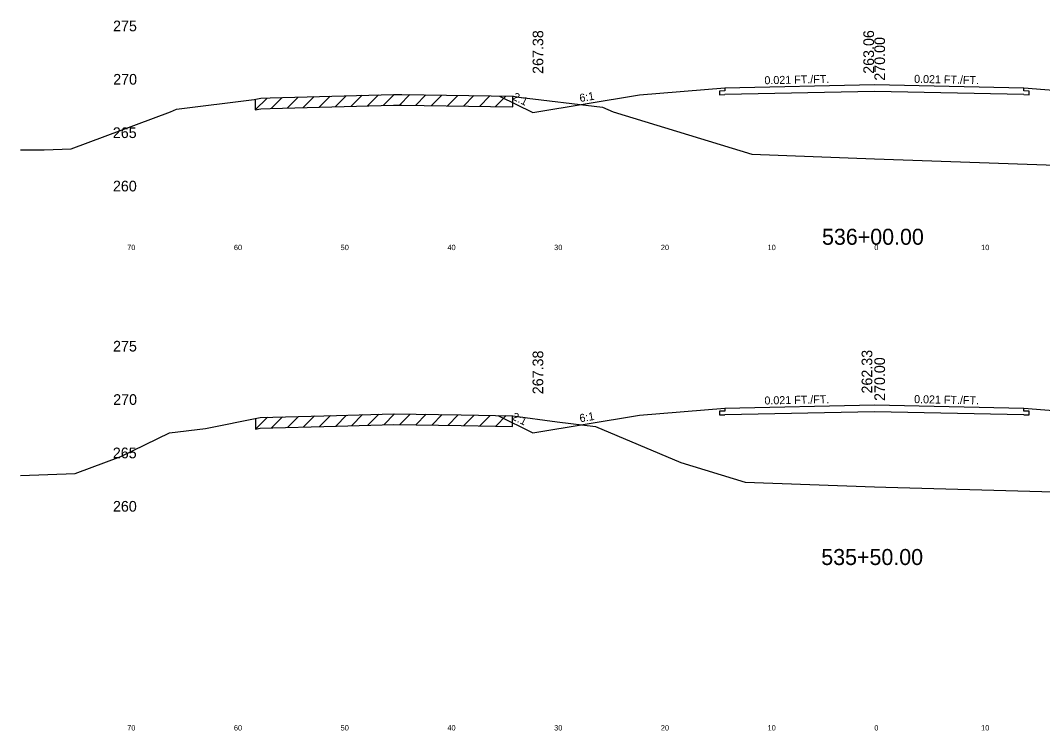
# Model space of a CAD drawing. Extents: x 1000 to 1162, y 999 to 8520.
# Drawn here: x 1000 to 1095.8, y 5599.5 to 5666 of the extents above; entities that cross this region are included whole.
import ezdxf

# ---------------------------------------------------------------- set-up
doc = ezdxf.new("R2010")
doc.units = 0
for name, color, linetype in [('Level 10', 7, 'Continuous'), ('Level 11', 7, 'Continuous'), ('Level 12', 7, 'Continuous'), ('Level 3', 7, 'Continuous'), ('Level 32', 7, 'Continuous'), ('Level 33', 7, 'Continuous'), ('Level 56', 7, 'Continuous'), ('Level 59', 7, 'Continuous'), ('Level 6', 7, 'Continuous'), ('Level 60', 7, 'Continuous'), ('Level 61', 7, 'Continuous'), ('Level 7', 7, 'Continuous')]:
    doc.layers.add(name, color=color, linetype=linetype)

msp = doc.modelspace()

# ---------------------------------------------------------------- linework, layer by layer
at = {"layer": 'Level 11'}
for p, q in [((1066, 5659.409), (1065.5, 5659.398)), ((1065.5, 5659.398), (1065.5, 5659.058)), ((1066, 5659.709), (1066, 5659.409)), ((1094, 5659.409), (1094, 5659.709)), ((1094.5, 5659.398), (1094, 5659.409)), ((1094.5, 5659.058), (1094.5, 5659.398)), ((1065.5, 5659.058), (1066, 5659.069)), ((1094, 5659.069), (1094.5, 5659.058)), ((1066, 5629.709), (1066, 5629.409)), ((1094, 5629.409), (1094, 5629.709)), ((1066, 5629.409), (1065.5, 5629.398)), ((1065.5, 5629.398), (1065.5, 5629.058)), ((1065.5, 5629.058), (1066, 5629.069)), ((1094.5, 5629.398), (1094, 5629.409)), ((1094, 5629.069), (1094.5, 5629.058)), ((1094.5, 5629.058), (1094.5, 5629.398))]:
    msp.add_line(p, q, dxfattribs=at)
at = {"layer": 'Level 12'}
for p, q in [((1080, 5659.36), (1066, 5659.069)), ((1094, 5659.069), (1080, 5659.36)), ((1080, 5629.36), (1066, 5629.069)), ((1094, 5629.069), (1080, 5629.36))]:
    msp.add_line(p, q, dxfattribs=at)
at = {"layer": 'Level 59'}
for p, q in [((1066, 5659.709), (1080, 5660)), ((1080, 5660), (1094, 5659.709)), ((1066, 5629.709), (1080, 5630)), ((1080, 5630), (1094, 5629.709))]:
    msp.add_line(p, q, dxfattribs=at)
at = {"layer": 'Level 6'}
for p, q in [((1058, 5659.042), (1066, 5659.709)), ((1094, 5659.709), (1102, 5659.042)), ((1058, 5629.042), (1066, 5629.709)), ((1094, 5629.709), (1102, 5629.042))]:
    msp.add_line(p, q, dxfattribs=at)
at = {"layer": 'Level 60'}
for p, q in [((1014.617, 5657.714), (1021.896, 5658.608)), ((1021.896, 5658.608), (1022.517, 5658.732)), ((1022.517, 5658.732), (1023.383, 5658.756)), ((1023.383, 5658.756), (1034.954, 5659.091)), ((1034.954, 5659.091), (1035.735, 5659.078)), ((1035.735, 5659.078), (1046.182, 5658.911)), ((1046.182, 5658.911), (1046.699, 5658.84)), ((1046.699, 5658.84), (1054.528, 5657.893)), ((1014.061, 5657.443), (1014.617, 5657.714)), ((1054.528, 5657.893), (1055.542, 5657.466)), ((1055.542, 5657.466), (1068.523, 5653.474)), ((1004.757, 5654), (1014.061, 5657.443)), ((1000, 5653.891), (1002.221, 5653.908)), ((1002.221, 5653.908), (1004.757, 5654)), ((1068.523, 5653.474), (1080, 5653.063)), ((1080, 5653.063), (1097.018, 5652.454)), ((1017.337, 5627.797), (1022.466, 5628.822)), ((1022.466, 5628.822), (1029.616, 5629.016)), ((1029.616, 5629.016), (1034.963, 5629.171)), ((1034.963, 5629.171), (1041.299, 5629.063)), ((1041.299, 5629.063), (1046.116, 5628.986)), ((1046.116, 5628.986), (1050.276, 5628.42)), ((1013.973, 5627.384), (1017.337, 5627.797)), ((1050.276, 5628.42), (1053.891, 5627.983)), ((1053.891, 5627.983), (1061.879, 5624.617)), ((1009.409, 5625.159), (1013.973, 5627.384)), ((1005.113, 5623.569), (1009.409, 5625.159)), ((1061.879, 5624.617), (1067.889, 5622.768)), ((1000, 5623.384), (1005.113, 5623.569)), ((1067.889, 5622.768), (1080, 5622.335)), ((1080, 5622.335), (1081.083, 5622.296)), ((1081.083, 5622.296), (1104.023, 5621.67))]:
    msp.add_line(p, q, dxfattribs=at)
at = {"layer": 'Level 61'}
for p, q in [((1023.12, 5658.749), (1022, 5657.629)), ((1022, 5658.629), (1022, 5657.629)), ((1024.53, 5658.789), (1023.5, 5657.759)), ((1026.03, 5658.833), (1025, 5657.803)), ((1027.53, 5658.876), (1026.5, 5657.846)), ((1029.03, 5658.92), (1028, 5657.89)), ((1030.53, 5658.963), (1029.5, 5657.933)), ((1032.03, 5659.007), (1031, 5657.977)), ((1033.53, 5659.05), (1032.5, 5658.02)), ((1035.027, 5659.09), (1034, 5658.064)), ((1036.484, 5659.066), (1035.5, 5658.082)), ((1037.984, 5659.042), (1037, 5658.058)), ((1039.484, 5659.018), (1038.5, 5658.034)), ((1040.984, 5658.994), (1040, 5658.01)), ((1042.484, 5658.97), (1041.5, 5657.986)), ((1043.984, 5658.946), (1043, 5657.962)), ((1045.484, 5658.922), (1044.5, 5657.938)), ((1046.138, 5657.911), (1046.138, 5658.911)), ((1022, 5657.629), (1022.517, 5657.732)), ((1022.517, 5657.732), (1023.383, 5657.756)), ((1023.383, 5657.756), (1034.954, 5658.091)), ((1034.954, 5658.091), (1035.735, 5658.078)), ((1035.735, 5658.078), (1046.138, 5657.911)), ((1023.137, 5628.841), (1022.033, 5627.736)), ((1022.033, 5628.736), (1022.033, 5627.736)), ((1024.56, 5628.879), (1023.533, 5627.851)), ((1026.06, 5628.92), (1025.033, 5627.892)), ((1027.56, 5628.961), (1026.533, 5627.933)), ((1029.06, 5629.001), (1028.033, 5627.973)), ((1030.562, 5629.044), (1029.533, 5628.014)), ((1032.062, 5629.087), (1031.033, 5628.057)), ((1033.562, 5629.131), (1032.533, 5628.101)), ((1035.058, 5629.17), (1034.033, 5628.144)), ((1036.516, 5629.145), (1035.533, 5628.162)), ((1038.016, 5629.119), (1037.033, 5628.136)), ((1039.516, 5629.093), (1038.533, 5628.11)), ((1041.016, 5629.068), (1040.033, 5628.085)), ((1042.517, 5629.043), (1041.533, 5628.059)), ((1044.017, 5629.019), (1043.033, 5628.035)), ((1045.517, 5628.995), (1044.533, 5628.011)), ((1046.113, 5627.986), (1046.113, 5628.986)), ((1022.032, 5627.736), (1022.466, 5627.822)), ((1022.466, 5627.822), (1029.616, 5628.016)), ((1029.616, 5628.016), (1034.963, 5628.171)), ((1034.963, 5628.171), (1041.299, 5628.063)), ((1041.299, 5628.063), (1046.113, 5627.986))]:
    msp.add_line(p, q, dxfattribs=at)
at = {"layer": 'Level 7'}
for p, q in [((1044.888, 5658.931), (1048, 5657.376)), ((1048, 5657.376), (1058, 5659.042)), ((1044.735, 5629.008), (1048, 5627.376)), ((1048, 5627.376), (1058, 5629.042))]:
    msp.add_line(p, q, dxfattribs=at)

# ---------------------------------------------------------------- texts
at = {"layer": 'Level 10'}
for s, p in [('263.06', (1079.968, 5661.014)), ('262.33', (1079.806, 5631.065))]:
    msp.add_text(s, height=1, rotation=90, dxfattribs=at).set_placement(p)
at = {"layer": 'Level 11'}
for s, p in [(' 275', (1008.307, 5665)), (' 270', (1008.319, 5660)), (' 265', (1008.284, 5655)), (' 260', (1008.295, 5650)), (' 275', (1008.307, 5635)), (' 270', (1008.319, 5630)), (' 265', (1008.284, 5625)), (' 260', (1008.295, 5620))]:
    msp.add_text(s, height=1, dxfattribs=at).set_placement(p)
at = {"layer": 'Level 3'}
for s, p in [('536+00.00', (1075.098, 5645)), ('535+50.00', (1075.028, 5615))]:
    msp.add_text(s, height=1.5, dxfattribs=at).set_placement(p)
at = {"layer": 'Level 32'}
for s, rotation, p in [('0.021 FT./FT.', 1.19158, (1069.709, 5660.036)), ('0.021 FT./FT.', 358.80842, (1083.72, 5660.173)), ('2:1', 333.43495, (1046.049, 5658.631)), ('6:1', 9.46232, (1052.435, 5658.368)), ('0.021 FT./FT.', 1.19158, (1069.709, 5630.036)), ('0.021 FT./FT.', 358.80842, (1083.72, 5630.173)), ('2:1', 333.43495, (1045.972, 5628.669)), ('6:1', 9.46232, (1052.435, 5628.368))]:
    msp.add_text(s, height=0.75, rotation=rotation, dxfattribs=at).set_placement(p)
at = {"layer": 'Level 33'}
for p in [(1048.985, 5661.008), (1048.98, 5631)]:
    msp.add_text('267.38', height=1, rotation=90, dxfattribs=at).set_placement(p)
at = {"layer": 'Level 56'}
for s, p in [('70', (1010, 5644.5)), ('60', (1020, 5644.5)), ('50', (1030, 5644.5)), ('40', (1040, 5644.5)), ('30', (1050, 5644.5)), ('20', (1060, 5644.5)), ('10', (1070, 5644.5)), ('0', (1080, 5644.5)), ('10', (1090, 5644.5)), ('70', (1010, 5599.5)), ('60', (1020, 5599.5)), ('50', (1030, 5599.5)), ('40', (1040, 5599.5)), ('30', (1050, 5599.5)), ('20', (1060, 5599.5)), ('10', (1070, 5599.5)), ('0', (1080, 5599.5)), ('10', (1090, 5599.5))]:
    msp.add_text(s, height=0.5, dxfattribs=at).set_placement(p)
at = {"layer": 'Level 59'}
for p in [(1081, 5660), (1081, 5630)]:
    msp.add_text(' 270.00', height=1, rotation=90, dxfattribs=at).set_placement(p)

doc.saveas('drawing.dxf')
